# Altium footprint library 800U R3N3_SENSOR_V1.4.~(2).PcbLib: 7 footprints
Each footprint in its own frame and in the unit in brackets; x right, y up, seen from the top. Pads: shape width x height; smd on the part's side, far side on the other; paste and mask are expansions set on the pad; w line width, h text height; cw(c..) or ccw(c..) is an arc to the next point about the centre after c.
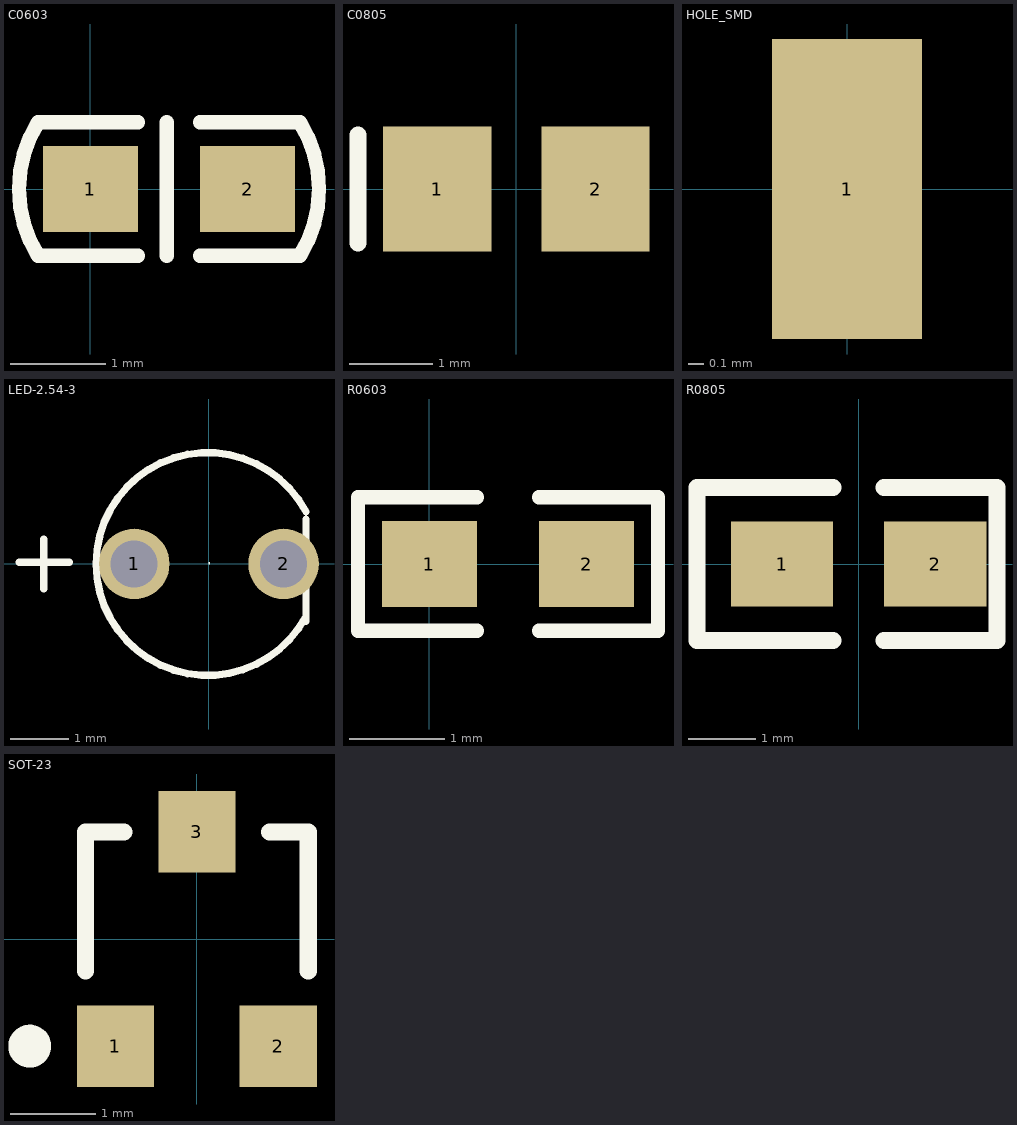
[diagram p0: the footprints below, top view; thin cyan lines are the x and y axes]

## C0603 [mm]
height 5.4
pads (2):
  rect 1x0.9 smd: 1(0,0) 2(1.65,0)
Top Overlay:
  lines w0.15: 0.5,-0.7 -0.55,-0.7 cw(c0.575,0) -0.55,0.7 0.5,0.7 ; 0.8,-0.7 0.8,0.7 ; 1.15,-0.7 2.2,-0.7 ccw(c1.075,0) 2.2,0.7 1.15,0.7

## C0805 [mm] "Chip Capacitor; Body 2.0 x"
height 1.1
pads (2):
  rect 1.3x1.5 smd: 1(-0.95,0) 2(0.95,0)
Top Overlay:
  lines w0.2: -1.9,-0.65 -1.9,0.65

## HOLE_SMD [mm]
height 5.4
pads (1):
  rect 1x2 smd: 1(0,0)

## LED-2.54-3 [mm]
pads (2):
  round 1.2 hole 0.8: 1(-1.27,0) 2(1.27,0)
Top Overlay:
  lines w0.01: -0.006,0.005 ccw(c0.003,0.01) -0.006,0.015
  lines w0.125: -3.23,0.03 -2.37,0.03 ; -2.81,-0.42 -2.81,0.42 ; 1.651,-0.978 1.651,0.762 ; 1.651,-0.89 cw(c-0.022,-0.001) 1.651,0.889

## R0603 [mm]
height 5.4
pads (2):
  rect 1x0.9 smd: 1(0,0) 2(1.65,0)
Top Overlay:
  lines w0.15: 0.5,-0.7 -0.75,-0.7 -0.75,0.7 0.5,0.7 ; 1.15,-0.7 2.4,-0.7 2.4,0.7 1.15,0.7

## R0805 [mil]
height 212.6
pads (2):
  rect 60x50 smd: 1(-45,0) 2(45,0)
Top Overlay:
  lines w10: -15,-45 -95,-45 -95,45 -15,45 ; 15,-45 81.3,-45 81.3,45 15,45

## SOT-23 [mm] "SOT-23; 3 Leads; Body 3.0 x 2.6 mm"
height 1.1
pads (3):
  rect 0.9x0.95 smd: 1(-0.95,-1.25) 2(0.95,-1.25) 3(0,1.25)
Top Overlay:
  circle w0.25: c-1.95,-1.25 r0.125
  lines w0.2: -1.3,-0.375 -1.3,1.25 -0.85,1.25 ; 0.85,1.25 1.3,1.25 1.3,-0.375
